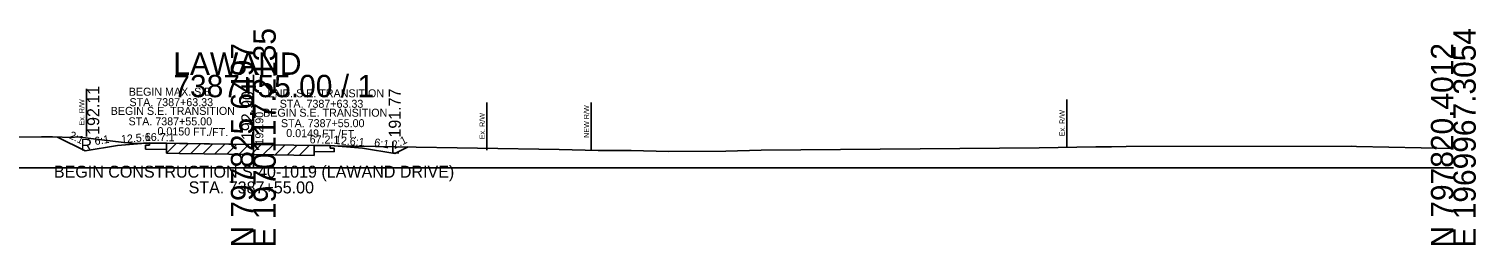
# Model space of a CAD drawing. Extents: x -26 to 303, y -10 to 1532.
# Drawn here: x 122 to 302.8, y -9.7 to 17.4 of the extents above; entities that cross this region are included whole.
import ezdxf

# ---------------------------------------------------------------- set-up
doc = ezdxf.new("R2010")
doc.units = 0
for name, color, linetype in [('RD_GPK_XS_Cell', 7, 'Continuous'), ('RD_XS_Base', 7, 'Continuous'), ('RD_XS_EarthShd', 7, 'Continuous'), ('RD_XS_ExGround', 7, 'Continuous'), ('RD_XS_ExPaveRet', 7, 'Continuous'), ('RD_XS_ExRW', 7, 'Continuous'), ('RD_XS_Misc_Line', 7, 'Continuous'), ('RD_XS_NewRW', 7, 'Continuous'), ('RD_XS_Pave', 7, 'Continuous'), ('RD_XS_PaveOvlay', 7, 'Continuous'), ('RD_XS_PaveShd', 7, 'Continuous'), ('RD_XS_TieSlope', 7, 'Continuous'), ('RD_XS_TX_Elev_EX', 7, 'Continuous'), ('RD_XS_TX_Elev_PR', 7, 'Continuous'), ('RD_XS_TX_Misc', 7, 'Continuous'), ('RD_XS_TX_MkPT', 7, 'Continuous'), ('RD_XS_TX_Notes', 7, 'Continuous'), ('RD_XS_TX_Profile', 7, 'Continuous'), ('RD_XS_TX_ShdSlope', 7, 'Continuous'), ('RD_XS_TX_Slope', 7, 'Continuous')]:
    doc.layers.add(name, color=color, linetype=linetype)

msp = doc.modelspace()

# ---------------------------------------------------------------- linework, layer by layer
at = {"layer": 'RD_GPK_XS_Cell'}
for p, q in [((150, 0), (150, 11.62)), ((0, 0), (150, 0)), ((150, 0), (300, 0))]:
    msp.add_line(p, q, dxfattribs=at)
at = {"layer": 'RD_XS_Base'}
for p, q in [((136.5, 2.81), (137, 2.8)), ((136.5, 2.33), (136.5, 2.81)), ((139.15, 2.29), (136.5, 2.33)), ((137, 2.8), (137, 3.1)), ((157.6, 2.01), (160.12, 1.97)), ((159.61, 2.46), (159.61, 2.76)), ((160.12, 2.45), (159.61, 2.46)), ((160.12, 1.97), (160.12, 2.45))]:
    msp.add_line(p, q, dxfattribs=at)
at = {"layer": 'RD_XS_EarthShd'}
for p, q in [((137, 3.1), (133, 2.78)), ((159.61, 2.76), (163.65, 2.44))]:
    msp.add_line(p, q, dxfattribs=at)
at = {"layer": 'RD_XS_ExGround'}
msp.add_lwpolyline([(114.94, 3.76), (123.52, 3.87), (124.9, 3.86), (127.35, 3.79), (127.96, 3.85), (133.82, 3.17), (135.27, 3.01), (136.28, 3.05), (139.15, 3.07), (140.76, 3.04), (150, 2.9), (157.6, 2.79), (188.23, 2.28), (193.1, 2.15), (197.24, 2.13), (201.9, 2.04), (209.07, 2.08), (213.49, 2.21), (248.22, 2.49), (255.31, 2.61), (257.28, 2.62), (259.12, 2.64), (287.3, 2.69), (287.91, 2.67), (300, 2.4)], dxfattribs=at)
at = {"layer": 'RD_XS_ExPaveRet'}
for p, q in [((139.15, 1.82), (139.15, 3.07)), ((139.15, 1.82), (140.76, 1.79)), ((157.6, 2.79), (157.6, 1.54)), ((140.76, 1.79), (150, 1.65)), ((150, 1.65), (157.6, 1.54))]:
    msp.add_line(p, q, dxfattribs=at)
at = {"layer": 'RD_XS_ExRW'}
for p, q in [((129.13, 9.89), (129.13, 3.89)), ((179.18, 8.18), (179.18, 2.18)), ((251.67, 8.55), (251.67, 2.55))]:
    msp.add_line(p, q, dxfattribs=at)
at = {"layer": 'RD_XS_Misc_Line'}
for p, q in [((139.15, 1.82), (140.39, 3.05)), ((140.66, 1.79), (141.9, 3.02)), ((142.17, 1.77), (143.41, 3)), ((143.68, 1.75), (144.92, 2.98)), ((145.19, 1.73), (146.43, 2.96)), ((146.7, 1.7), (147.94, 2.93)), ((148.21, 1.68), (149.45, 2.91)), ((149.72, 1.66), (150.96, 2.89)), ((151.23, 1.64), (152.47, 2.87)), ((152.74, 1.61), (153.98, 2.85)), ((154.25, 1.59), (155.49, 2.82)), ((155.76, 1.57), (157, 2.8))]:
    msp.add_line(p, q, dxfattribs=at)
at = {"layer": 'RD_XS_NewRW'}
msp.add_line((192.23, 8.18), (192.23, 2.18), dxfattribs=at)
at = {"layer": 'RD_XS_Pave'}
for q in [(139, 3.07), (157.6, 2.79)]:
    msp.add_line((150, 2.9), q, dxfattribs=at)
at = {"layer": 'RD_XS_PaveOvlay'}
for p, q in [((139.15, 3.07), (140.76, 3.04)), ((139.15, 3.07), (139.15, 2.29)), ((140.76, 3.04), (150, 2.9)), ((150, 2.9), (157.6, 2.79)), ((157.6, 2.79), (157.6, 2.01))]:
    msp.add_line(p, q, dxfattribs=at)
at = {"layer": 'RD_XS_PaveShd'}
for p, q in [((139, 3.07), (137, 3.1)), ((157.6, 2.79), (159.61, 2.76))]:
    msp.add_line(p, q, dxfattribs=at)
at = {"layer": 'RD_XS_TieSlope'}
for p, q in [((128.99, 2.11), (125.53, 3.84)), ((133, 2.78), (128.99, 2.11)), ((163.65, 2.44), (167.68, 1.77)), ((167.68, 1.77), (169.34, 2.6))]:
    msp.add_line(p, q, dxfattribs=at)

# ---------------------------------------------------------------- texts
at = {"layer": 'RD_GPK_XS_Cell'}
for s, p in [('E 1970117.2135', (152.8, -10)), ('E 1969967.3054', (302.8, -10)), ('N 797825.6497', (150, -10)), ('N 797820.4012', (300, -10))]:
    msp.add_text(s, height=2.8, rotation=90, dxfattribs=at).set_placement(p)
for s, p in [('LAWAND', (140, 11.62)), ('7387+55.00 / 1', (140, 8.82))]:
    msp.add_text(s, height=2.8, dxfattribs=at).set_placement(p)
at = {"layer": 'RD_XS_ExRW'}
for p in [(128.88, 5.28), (178.93, 3.56), (251.42, 3.93)]:
    msp.add_text('Ex. R/W ', height=0.65, rotation=90, dxfattribs=at).set_placement(p)
at = {"layer": 'RD_XS_NewRW'}
msp.add_text('NEW R/W ', height=0.65, rotation=90, dxfattribs=at).set_placement((191.97, 3.73))
at = {"layer": 'RD_XS_TX_Elev_EX'}
msp.add_text('192.90', height=1, rotation=90, dxfattribs=at).set_placement((151.25, 2.9))
at = {"layer": 'RD_XS_TX_Elev_PR'}
msp.add_text(' 192.90', height=1.5, rotation=90, dxfattribs=at).set_placement((150, 2.9))
at = {"layer": 'RD_XS_TX_Misc'}
for s, p in [('192.11', (130.74, 4.11)), ('191.77', (168.43, 3.77))]:
    msp.add_text(s, height=1.5, rotation=90, dxfattribs=at).set_placement(p)
at = {"layer": 'RD_XS_TX_MkPT'}
for s, p in [('R', (128.4, 2.11)), ('L', (167.17, 1.77))]:
    msp.add_text(s, height=1.5, dxfattribs=at).set_placement(p)
at = {"layer": 'RD_XS_TX_Notes'}
for s, height, p in [('BEGIN MAX. S.E.', 1, (134.43, 9.01)), ('END. S.E. TRANSITION', 1, (151.78, 8.81)), ('BEGIN S.E. TRANSITION', 1, (132.17, 6.61)), ('STA. 7387+63.33', 1, (134.52, 7.7)), ('BEGIN S.E. TRANSITION', 1, (151.22, 6.38)), ('STA. 7387+63.33', 1, (153.3, 7.5)), ('STA. 7387+55.00', 1, (134.4, 5.3)), ('STA. 7387+55.00', 1, (153.45, 5.07)), ('BEGIN CONSTRUCTION S-40-1019 (LAWAND DRIVE)', 1.5, (125.07, -1.25)), ('STA. 7387+55.00', 1.5, (141.91, -3.22))]:
    msp.add_text(s, height=height, dxfattribs=at).set_placement(p)
at = {"layer": 'RD_XS_TX_Profile'}
for s, rotation, p in [('66.7:1', 359.1412, (136.43, 3.36)), ('67.2:1', 359.1473, (157.03, 3.05))]:
    msp.add_text(s, height=1, rotation=rotation, dxfattribs=at).set_placement(p)
at = {"layer": 'RD_XS_TX_ShdSlope'}
for s, rotation, p in [('12.5:1', 4.571, (133.5, 3.07)), ('12.6:1', 355.4613, (160.17, 2.97))]:
    msp.add_text(s, height=1, rotation=rotation, dxfattribs=at).set_placement(p)
at = {"layer": 'RD_XS_TX_Slope'}
for s, rotation, p in [('2:1', 333.4496, (126.85, 3.74)), ('6:1', 9.4564, (130.22, 2.82)), ('0.0150 FT./FT.', 359.1412, (138.01, 4.08)), ('0.0149 FT./FT.', 359.1473, (154.11, 3.84)), ('6:1', 350.6094, (165.05, 2.71)), ('2:1', 26.3878, (167.65, 2.32))]:
    msp.add_text(s, height=1, rotation=rotation, dxfattribs=at).set_placement(p)

doc.saveas('drawing.dxf')
